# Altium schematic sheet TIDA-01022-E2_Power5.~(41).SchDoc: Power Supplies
size 431 x 279 mm; Date: Not shown in title block; ApprovedBy: Not shown in title block; CheckedBy: Not shown in title block; Author: Not shown in title block; CompanyName: Not shown in title block; DrawnBy: Avinash N; Engineer: Not shown in title block; Organization: Not shown in title block; Address1: Not shown in title block; Address2: Not shown in title block; Address3: Not shown in title block; Address4: Not shown in title block; DocumentNumber: 1; Revision: Use project parameter SCH_Rev; SheetNumber: 25; SheetTotal: 26; PageSetup: Record=PageOptions¦CenterHorizontal=True¦CenterVertical=True¦PrintScale=1.00¦XCorrection=1.00¦YCorrection=1.00¦PrintKind=0¦BorderSize=5000000¦LeftOffset=0¦BottomOffset=0¦Orientation=2¦PaperLength=1000¦PaperWidth=1000¦Scale=100¦PaperSource=15¦PrintQuality=600¦MediaType=1¦DitherType=10¦PaperKind=Letter¦PrintScaleMode=1
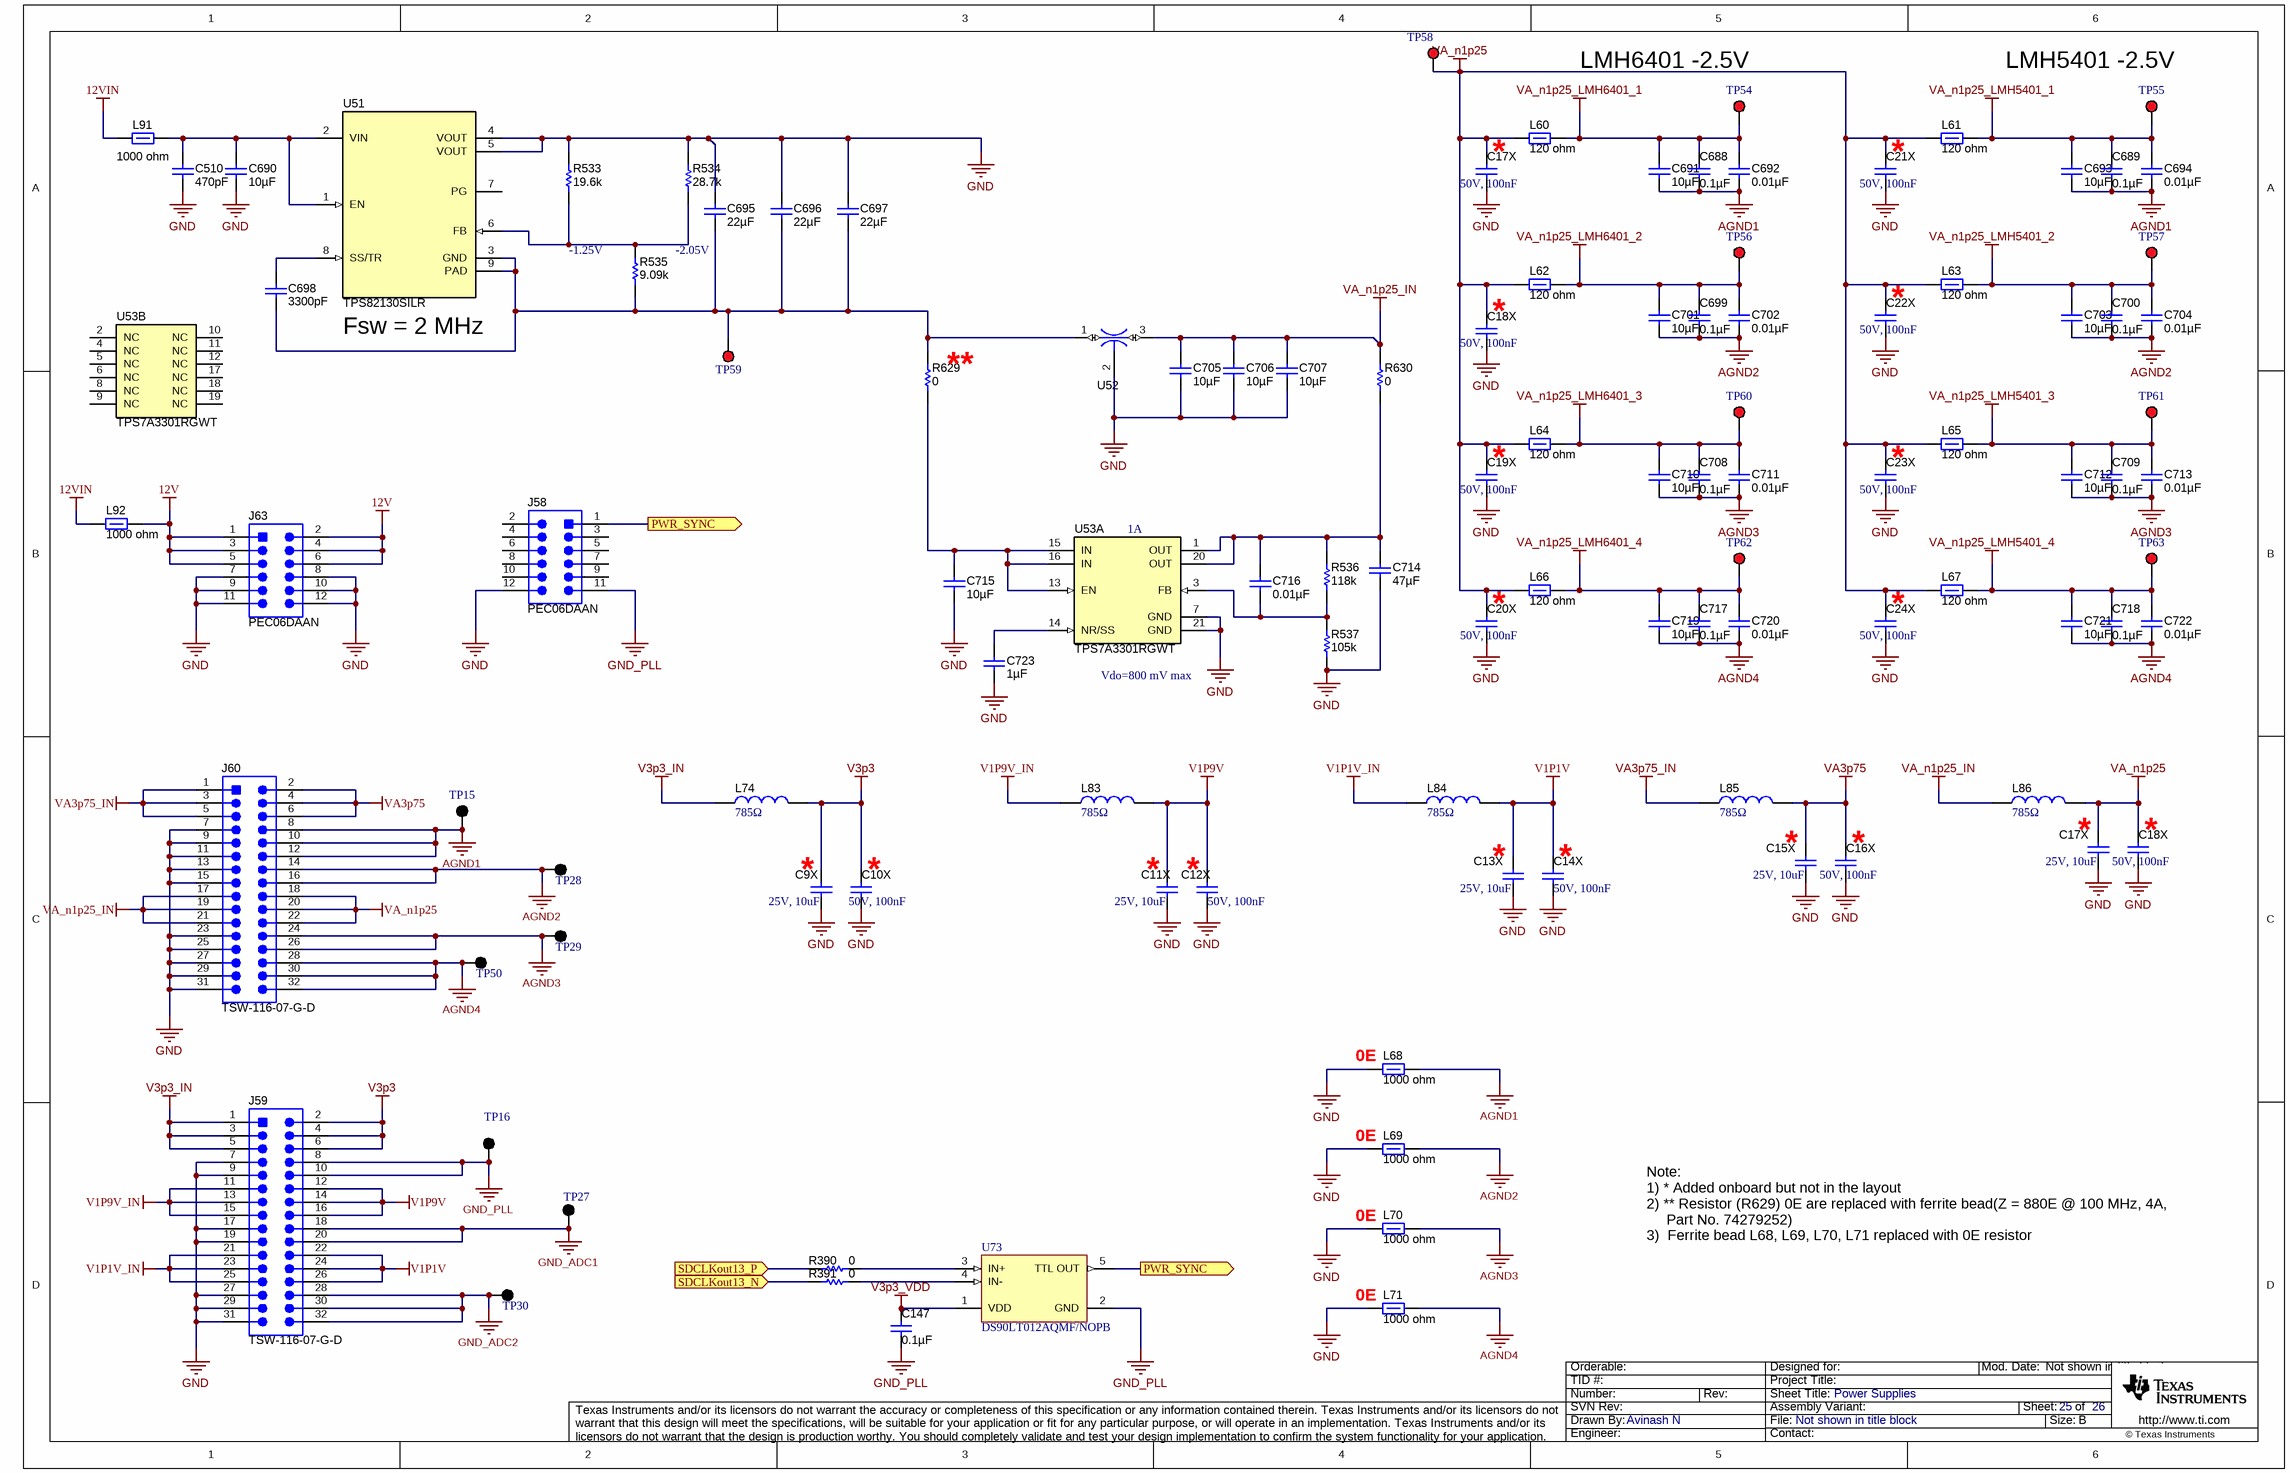
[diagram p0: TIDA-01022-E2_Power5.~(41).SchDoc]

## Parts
(Parts that share a designator on the sheet are numbered #1, #2 ... from top to bottom, then left to right.)
C9X  25V, 10uF  [1206_3.2x1.6x1.6mm]
C10X  50V, 100nF  [0603_1.6x0.8x0.8mm_Reflow Soldering]
C11X  25V, 10uF  [1206_3.2x1.6x1.6mm]
C12X  50V, 100nF  [0603_1.6x0.8x0.8mm_Reflow Soldering]
C13X  25V, 10uF  [1206_3.2x1.6x1.6mm]
C14X  50V, 100nF  [0603_1.6x0.8x0.8mm_Reflow Soldering]
C15X  25V, 10uF  [1206_3.2x1.6x1.6mm]
C16X  50V, 100nF  [0603_1.6x0.8x0.8mm_Reflow Soldering]
C17X#1  50V, 100nF  [0603_1.6x0.8x0.8mm_Reflow Soldering]
C17X#2  25V, 10uF  [1206_3.2x1.6x1.6mm]
C18X#1  50V, 100nF  [0603_1.6x0.8x0.8mm_Reflow Soldering]
C18X#2  50V, 100nF  [0603_1.6x0.8x0.8mm_Reflow Soldering]
C19X  50V, 100nF  [0603_1.6x0.8x0.8mm_Reflow Soldering]
C20X  50V, 100nF  [0603_1.6x0.8x0.8mm_Reflow Soldering]
C21X  50V, 100nF  [0603_1.6x0.8x0.8mm_Reflow Soldering]
C22X  50V, 100nF  [0603_1.6x0.8x0.8mm_Reflow Soldering]
C23X  50V, 100nF  [0603_1.6x0.8x0.8mm_Reflow Soldering]
C24X  50V, 100nF  [0603_1.6x0.8x0.8mm_Reflow Soldering]
C147  ValueDisplayed: 0.1µF  [0603]  (hidden comment: CGA3E2X7R1H104K080AA)
C510  ValueDisplayed: 470pF  [0402]  (hidden comment: GRM1555C1H471JA01D)
C688  ValueDisplayed: 0.1µF  [0603]  (hidden comment: CGA3E2X7R1H104K080AA)
C689  ValueDisplayed: 0.1µF  [0603]  (hidden comment: CGA3E2X7R1H104K080AA)
C690  ValueDisplayed: 10µF  [1206_190]  (hidden comment: C3216X7R1E106M160AE)
C691  ValueDisplayed: 10µF  [1206_190]  (hidden comment: C3216X7R1E106M160AE)
C692  ValueDisplayed: 0.01µF  [0603]  (hidden comment: GCM188R71H103KA37D)
C693  ValueDisplayed: 10µF  [1206_190]  (hidden comment: C3216X7R1E106M160AE)
C694  ValueDisplayed: 0.01µF  [0603]  (hidden comment: GCM188R71H103KA37D)
C695  ValueDisplayed: 22µF  [0805_HV]  (hidden comment: JMK212BJ226MG-T)
C696  ValueDisplayed: 22µF  [0805_HV]  (hidden comment: JMK212BJ226MG-T)
C697  ValueDisplayed: 22µF  [0805_HV]  (hidden comment: JMK212BJ226MG-T)
C698  ValueDisplayed: 3300pF  [0603]  (hidden comment: GRM1885C1H332JA01D)
C699  ValueDisplayed: 0.1µF  [0603]  (hidden comment: CGA3E2X7R1H104K080AA)
C700  ValueDisplayed: 0.1µF  [0603]  (hidden comment: CGA3E2X7R1H104K080AA)
C701  ValueDisplayed: 10µF  [1206_190]  (hidden comment: C3216X7R1E106M160AE)
C702  ValueDisplayed: 0.01µF  [0603]  (hidden comment: GCM188R71H103KA37D)
C703  ValueDisplayed: 10µF  [1206_190]  (hidden comment: C3216X7R1E106M160AE)
C704  ValueDisplayed: 0.01µF  [0603]  (hidden comment: GCM188R71H103KA37D)
C705  ValueDisplayed: 10µF  [1206_190]  (hidden comment: C3216X7R1E106M160AE)
C706  ValueDisplayed: 10µF  [1206_190]  (hidden comment: C3216X7R1E106M160AE)
C707  ValueDisplayed: 10µF  [1206_190]  (hidden comment: C3216X7R1E106M160AE)
C708  ValueDisplayed: 0.1µF  [0603]  (hidden comment: CGA3E2X7R1H104K080AA)
C709  ValueDisplayed: 0.1µF  [0603]  (hidden comment: CGA3E2X7R1H104K080AA)
C710  ValueDisplayed: 10µF  [1206_190]  (hidden comment: C3216X7R1E106M160AE)
C711  ValueDisplayed: 0.01µF  [0603]  (hidden comment: GCM188R71H103KA37D)
C712  ValueDisplayed: 10µF  [1206_190]  (hidden comment: C3216X7R1E106M160AE)
C713  ValueDisplayed: 0.01µF  [0603]  (hidden comment: GCM188R71H103KA37D)
C714  ValueDisplayed: 47µF  [0805_HV]  (hidden comment: GRM219R60G476ME44D)
C715  ValueDisplayed: 10µF  [1206_190]  (hidden comment: C3216X7R1E106M160AE)
C716  ValueDisplayed: 0.01µF  [0603]  (hidden comment: GRM188R71H103KA01D)
C717  ValueDisplayed: 0.1µF  [0603]  (hidden comment: CGA3E2X7R1H104K080AA)
C718  ValueDisplayed: 0.1µF  [0603]  (hidden comment: CGA3E2X7R1H104K080AA)
C719  ValueDisplayed: 10µF  [1206_190]  (hidden comment: C3216X7R1E106M160AE)
C720  ValueDisplayed: 0.01µF  [0603]  (hidden comment: GCM188R71H103KA37D)
C721  ValueDisplayed: 10µF  [1206_190]  (hidden comment: C3216X7R1E106M160AE)
C722  ValueDisplayed: 0.01µF  [0603]  (hidden comment: GCM188R71H103KA37D)
C723  ValueDisplayed: 1µF  [0805_HV]  (hidden comment: 08053D105KAT2A)
J58  PEC06DAAN  [CONN_PEC06DAAN]
J59  TSW-116-07-G-D  [TSW-116-07-G-D]
J60  TSW-116-07-G-D  [TSW-116-07-G-D]
J63  PEC06DAAN  [CONN_PEC06DAAN]
L60  ValueDisplayed: 120 ohm  [0603]  (hidden comment: BLM18SG121TN1D)
L61  ValueDisplayed: 120 ohm  [0603]  (hidden comment: BLM18SG121TN1D)
L62  ValueDisplayed: 120 ohm  [0603]  (hidden comment: BLM18SG121TN1D)
L63  ValueDisplayed: 120 ohm  [0603]  (hidden comment: BLM18SG121TN1D)
L64  ValueDisplayed: 120 ohm  [0603]  (hidden comment: BLM18SG121TN1D)
L65  ValueDisplayed: 120 ohm  [0603]  (hidden comment: BLM18SG121TN1D)
L66  ValueDisplayed: 120 ohm  [0603]  (hidden comment: BLM18SG121TN1D)
L67  ValueDisplayed: 120 ohm  [0603]  (hidden comment: BLM18SG121TN1D)
L68  ValueDisplayed: 1000 ohm  [1806_HighSpeed]  (hidden comment: BLM41PG102SN1L)
L69  ValueDisplayed: 1000 ohm  [1806_HighSpeed]  (hidden comment: BLM41PG102SN1L)
L70  ValueDisplayed: 1000 ohm  [1806_HighSpeed]  (hidden comment: BLM41PG102SN1L)
L71  ValueDisplayed: 1000 ohm  [1806_HighSpeed]  (hidden comment: BLM41PG102SN1L)
L74  785Ω  [WE-CBF_1812_High Current]
L83  785Ω  [WE-CBF_1812_High Current]
L84  785Ω  [WE-CBF_1812_High Current]
L85  785Ω  [WE-CBF_1812_High Current]
L86  785Ω  [WE-CBF_1812_High Current]
L91  ValueDisplayed: 1000 ohm  [1806_HighSpeed]  (hidden comment: BLM41PG102SN1L)
L92  ValueDisplayed: 1000 ohm  [1806_HighSpeed]  (hidden comment: BLM41PG102SN1L)
R390  ValueDisplayed: 0  [0402]  (hidden comment: CRCW04020000Z0ED)
R391  ValueDisplayed: 0  [0402]  (hidden comment: CRCW04020000Z0ED)
R533  ValueDisplayed: 19.6k  [0402]  (hidden comment: CRCW040219K6FKED)
R534  ValueDisplayed: 28.7k  [0402]  (hidden comment: CRCW040228K7FKED)
R535  ValueDisplayed: 9.09k  [0402]  (hidden comment: CRCW04029K09FKED)
R536  ValueDisplayed: 118k  [0402]  (hidden comment: CRCW0402118KFKED)
R537  ValueDisplayed: 105k  [0402]  (hidden comment: CRCW0402105KFKED)
R629  ValueDisplayed: 0  [1206]  (hidden comment: CRCW12060000Z0EA)
R630  ValueDisplayed: 0  [1206]  (hidden comment: CRCW12060000Z0EA)
TP15  5001  [Keystone5001]  (value not drawn)
TP16  5001  [Keystone5001]  (value not drawn)
TP27  5001  [Keystone5001]  (value not drawn)
TP28  5001  [Keystone5001]  (value not drawn)
TP29  5001  [Keystone5001]  (value not drawn)
TP30  5001  [Keystone5001]  (value not drawn)
TP50  5001  [Keystone5001]  (value not drawn)
TP54  5000  [Keystone5000]  (value not drawn)
TP55  5000  [Keystone5000]  (value not drawn)
TP56  5000  [Keystone5000]  (value not drawn)
TP57  5000  [Keystone5000]  (value not drawn)
TP58  5000  [Keystone5000]  (value not drawn)
TP59  5000  [Keystone5000]  (value not drawn)
TP60  5000  [Keystone5000]  (value not drawn)
TP61  5000  [Keystone5000]  (value not drawn)
TP62  5000  [Keystone5000]  (value not drawn)
TP63  5000  [Keystone5000]  (value not drawn)
U51  TPS82130SILR  [SIL0008D_SMD]
U52  NFM31PC276B0J3L  [Murata_NFM31P]  (value not drawn)
U53  TPS7A3301RGWT  [RGW0020A]  (parts A,B of 2)
U73  DS90LT012AQMF/NOPB  [MF05A_N]

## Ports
PWR_SYNC (out), SDCLKout13_N (in), SDCLKout13_P (in)

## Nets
12V: J63.1 J63.2 J63.3 J63.4 J63.5 J63.6 L92.1
12VIN: L91.1 L92.2
AGND1: C688.2 C689.2 C691.1 C692.2 C693.1 C694.2 J60.8 J60.10 J60.12 L68.2 TP15.1
AGND2: C699.2 C700.2 C701.1 C702.2 C703.1 C704.2 J60.14 J60.16 L69.2 TP28.1
AGND3: C708.2 C709.2 C710.1 C711.2 C712.1 C713.2 J60.24 J60.26 L70.2 TP29.1
AGND4: C717.2 C718.2 C719.1 C720.2 C721.1 C722.2 J60.28 J60.30 J60.32 L71.2 TP50.1
GND: C9X.1 C10X.1 C11X.1 C12X.1 C13X.1 C14X.1 C15X.1 C16X.1 C17X#1.1 C17X#2.1 C18X#1.1 C18X#2.1 C19X.1 C20X.1 C21X.1 C22X.1 C23X.1 C24X.1 C510.2 C690.2 C695.1 C696.1 C697.1 C705.1 C706.1 C707.1 C714.2 C715.1 C723.2 J58.12 J59.7 J59.9 J59.17 J59.19 J59.27 J59.29 J59.31 J60.7 J60.9 J60.11 J60.13 J60.15 J60.23 J60.25 J60.27 J60.29 J60.31 J63.7 J63.8 J63.9 J63.10 J63.11 J63.12 L68.1 L69.1 L70.1 L71.1 R533.2 R534.2 R537.1 U51.4(VOUT) U51.5(VOUT) U52.2 U53.7(GND) U53.21(GND)
GND_ADC1: J59.18 J59.20 TP27.1
GND_ADC2: J59.28 J59.30 J59.32 TP30.1
GND_PLL: C147.2 J58.11 J59.8 J59.10 TP16.1 U73.2(GND)
V1P1V: C13X.2 C14X.2 J59.22 J59.24 J59.26 L84.2
V1P1V_IN: J59.21 J59.23 J59.25 L84.1
V1P9V: C11X.2 C12X.2 J59.12 J59.14 J59.16 L83.2
V1P9V_IN: J59.11 J59.13 J59.15 L83.1
V3p3: C9X.2 C10X.2 J59.2 J59.4 J59.6 L74.2
V3p3_IN: J59.1 J59.3 J59.5 L74.1
V3p3_VDD: C147.1 U73.1(VDD)
VA3p75: C15X.2 C16X.2 J60.2 J60.4 J60.6 L85.2
VA3p75_IN: J60.1 J60.3 J60.5 L85.1
VA_n1p25: C17X#1.2 C17X#2.2 C18X#1.2 C18X#2.2 C19X.2 C20X.2 C21X.2 C22X.2 C23X.2 C24X.2 J60.18 J60.20 J60.22 L60.1 L61.1 L62.1 L63.1 L64.1 L65.1 L66.1 L67.1 L86.2 TP58.1
VA_n1p25_IN: C705.2 C706.2 C707.2 J60.17 J60.19 J60.21 L86.1 R630.2 U52.3
VA_n1p25_LMH5401_1: C689.1 C693.2 C694.1 L61.2 TP55.1
VA_n1p25_LMH5401_2: C700.1 C703.2 C704.1 L63.2 TP57.1
VA_n1p25_LMH5401_3: C709.1 C712.2 C713.1 L65.2 TP61.1
VA_n1p25_LMH5401_4: C718.1 C721.2 C722.1 L67.2 TP63.1
VA_n1p25_LMH6401_1: C688.1 C691.2 C692.1 L60.2 TP54.1
VA_n1p25_LMH6401_2: C699.1 C701.2 C702.1 L62.2 TP56.1
VA_n1p25_LMH6401_3: C708.1 C710.2 C711.1 L64.2 TP60.1
VA_n1p25_LMH6401_4: C717.1 C719.2 C720.1 L66.2 TP62.1
PWR_SYNC: J58.1 U73.5(TTL_OUT) ; port PWR_SYNC
SDCLKout13_N: R391.1 ; port SDCLKout13_N
SDCLKout13_P: R390.1 ; port SDCLKout13_P
NetC510_1: C510.1 C690.1 L91.2 U51.1(EN) U51.2(VIN)
NetC695_2: C695.2 C696.2 C697.2 C698.1 R535.1 R629.2 TP59.1 U51.3(GND) U51.9(PAD) U52.1
NetC698_2: C698.2 U51.8(SS/TR)
NetC714_1: C714.1 C716.1 R536.2 R630.1 U53.1(OUT) U53.20(OUT)
NetC715_2: C715.2 R629.1 U53.13(EN) U53.15(IN) U53.16(IN)
NetC716_2: C716.2 R536.1 R537.2 U53.3(FB)
NetC723_1: C723.1 U53.14(NR/SS)
NetR390_2: R390.2 U73.3(IN+)
NetR391_2: R391.2 U73.4(IN-)
NetR533_1: R533.1 R534.1 R535.2 U51.6(FB)

Not connected (* = marked no-connect by the designer): J58 2 3 4 5 6 7 8 9 10; U51 7(PG); U53 2(NC) 4(NC) 5(NC) 6(NC) 8(NC) 9(NC) 10(NC) 11(NC) 12(NC) 17(NC) 18(NC) 19(NC)

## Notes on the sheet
- (near TP54) LMH6401 -2.5V
- (near TP55) LMH5401 -2.5V
- (near C17X#1) *
- (near C21X) *
- (near R535) -1.25V
- -2.05V
- (near C22X) *
- (near U51) Fsw = 2 MHz
- (near R629) *
- (near C18X#1) *
- (near C19X) *
- (near C23X) *
- (near U53) 1A
- (near C20X) *
- (near C24X) *
- (near U53) Vdo=800 mV max
- (near C17X#2) *
- (near C18X#2) *
- (near C9X) *
- (near C10X) *
- (near C11X) *
- (near C12X) *
- (near C13X) *
- (near C14X) *
- (near C15X) *
- (near C16X) *
- (near L68) 0E
- (near L69) 0E
- (near L70) 0E
- (near L71) 0E
- Note:
  1) * Added onboard but not in the layout
  2) ** Resistor (R629) 0E are replaced with ferrite bead(Z = 880E @ 100 MHz, 4A,
  Part No. 74279252)
  3)  Ferrite bead L68, L69, L70, L71 replaced with 0E resistor

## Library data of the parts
C9X C11X C13X C15X C17X#2 = 885012208069: WCAP-CSGP Ceramic Capacitors, 1206, X7R, 25V, 10uF; Rated Voltage: 25V DC
C10X C12X C14X C16X C17X#1 C18X#1 C18X#2 C19X C20X C21X C22X C23X C24X = 885012206095: WCAP-CSGP Ceramic Capacitors, 0603, X7R, 50V, 100nF; Rated Voltage: 50V DC
C147 C688 C689 C699 C700 C708 C709 C717 C718 = CGA3E2X7R1H104K080AA: CAP, CERM, 0.1 µF, 50 V, +/- 10%, X7R, AEC-Q200 Grade 1, 0603; Manufacturer: TDK; Polarized: N; CompType: Capacitor; Value: 0.1uF; U/M: EA; Cap_F: 0.0000001; Tolerance_%: 10; ESR_ohm: 0.0296; Value1: 0.0296 ohm; VDC_V: 50; Value2: 50V; IRMS_A: 0.97199; TaMin_C: -55; TaMax_C: 125; SizeArea_mm2: 1.28; SizeAreaWB_mm2: 4.68; SizeX_mm: 1.6; SizeY_mm: 0.8; SizeZ_mm: 1; AEC Category: Q200; AEC Qualified: Y
C510 = GRM1555C1H471JA01D: CAP, CERM, 470 pF, 50 V, +/- 5%, C0G/NP0, 0402; Manufacturer: MuRata; Polarized: N; CompType: Capacitor; Value: 470pF; U/M: EA; Cap_F: 0.00000000047; Tolerance_%: 5; Value1: Unknown; VDC_V: 50; Value2: 50V; TaMin_C: -55; TaMax_C: 125; SizeArea_mm2: 0.5; SizeAreaWB_mm2: 3; SizeX_mm: 1; SizeZ_mm: 0.6; AEC Category: Q200
C690 C691 C693 C701 C703 C705-C707 C710 C712 C715 C719 C721 = C3216X7R1E106M160AE: CAP, CERM, 10 µF, 25 V, +/- 20%, X7R, 1206_190; Manufacturer: TDK; Polarized: N; CompType: Capacitor; Value: 10uF; U/M: EA; Cap_F: 0.00001; Tolerance_%: 20; Value1: Unknown; VDC_V: 25; Value2: 25V; TaMin_C: -55; TaMax_C: 125; Cap_Case: 1206; SizeArea_mm2: 5.12; SizeAreaWB_mm2: 10.92; SizeX_mm: 3.2; SizeY_mm: 1.6; SizeZ_mm: 1.9; AEC Category: Q200
C692 C694 C702 C704 C711 C713 C720 C722 = GCM188R71H103KA37D: CAP, CERM, 0.01 µF, 50 V, +/- 10%, X7R, AEC-Q200 Grade 1, 0603; Manufacturer: MuRata; Polarized: N; CompType: Capacitor; Value: 0.01uF; U/M: EA; Cap_F: 0.00000001; Tolerance_%: 10; Value1: Unknown; VDC_V: 50; Value2: 50V; TaMin_C: -55; TaMax_C: 125; SizeArea_mm2: 1.28; SizeAreaWB_mm2: 4.68; SizeX_mm: 1.6; SizeY_mm: 0.8; SizeZ_mm: 1; AEC Category: Q200; AEC Qualified: Y
C695-C697 = JMK212BJ226MG-T: CAP, CERM, 22 µF, 6.3 V, +/- 20%, X5R, 0805; Manufacturer: Taiyo Yuden; Polarized: N; CompType: Capacitor; Value: 22uF; U/M: EA; Cap_F: 0.000022; Tolerance_%: 20; Value1: Unknown; VDC_V: 6.3; Value2: 6.3V; TaMin_C: -55; TaMax_C: 85; Cap_Case: 0805; SizeArea_mm2: 2.5; SizeAreaWB_mm2: 6.75; SizeX_mm: 2; SizeY_mm: 1.25; SizeZ_mm: 1.45; AEC Category: Q200
C698 = GRM1885C1H332JA01D: CAP, CERM, 3300 pF, 50 V, +/- 5%, C0G/NP0, 0603; Manufacturer: MuRata; Polarized: N; CompType: Capacitor; Value: 3300pF; U/M: EA; Cap_F: 0.0000000033; Tolerance_%: 5; Value1: Unknown; VDC_V: 50; Value2: 50V; TaMin_C: -55; TaMax_C: 125; SizeArea_mm2: 1.28; SizeAreaWB_mm2: 4.68; SizeX_mm: 1.6; SizeY_mm: 0.8; SizeZ_mm: 1; AEC Category: Q200
C714 = GRM219R60G476ME44D: CAP, CERM, 47 µF, 4 V, +/- 20%, X5R, 0805; Manufacturer: MuRata; Polarized: N; CompType: Capacitor; Value: 47uF; U/M: EA; Cap_F: 0.000047; Tolerance_%: 20; Value1: Unknown; VDC_V: 4; Value2: 4V; TaMin_C: -55; TaMax_C: 85; Cap_Case: 0805; SizeArea_mm2: 2.5; SizeAreaWB_mm2: 6.75; SizeX_mm: 2; SizeY_mm: 1.25; SizeZ_mm: 1.45; AEC Category: Q200
C716 = GRM188R71H103KA01D: CAP, CERM, 0.01 µF, 50 V, +/- 10%, X7R, 0603; Manufacturer: MuRata; Polarized: N; CompType: Capacitor; Value: 0.01uF; U/M: EA; Cap_F: 0.00000001; Tolerance_%: 10; Value1: Unknown; VDC_V: 50; Value2: 50V; TaMin_C: -55; TaMax_C: 125; SizeArea_mm2: 1.28; SizeAreaWB_mm2: 4.68; SizeX_mm: 1.6; SizeY_mm: 0.8; SizeZ_mm: 1; AEC Category: Q200
C723 = 08053D105KAT2A: CAP, CERM, 1 µF, 25 V, +/- 10%, X5R, 0805; Manufacturer: AVX; Polarized: N; CompType: Capacitor; Value: 1uF; U/M: EA; Cap_F: 0.000001; Tolerance_%: 10; ESR_ohm: 0.012; Value1: 0.012 ohm; VDC_V: 25; Value2: 25V; TaMin_C: -55; TaMax_C: 85; Cap_Case: 0805; SizeArea_mm2: 2.5; SizeAreaWB_mm2: 6.75; SizeX_mm: 2; SizeY_mm: 1.25; SizeZ_mm: 1.45; AEC Category: Q200
J58 J63 = PEC06DAAN: Header, 100mil, 6x2, Tin, TH; Manufacturer: Sullins Connector Solutions; SymbolCreator: a0412235; Pitch_mm: 2.54; Gender: Male; Shrouded: N; Row_Count: 2; Current_A: 3; Voltage_V: 1800; Cert_UL: Y; Green_Lifecycle: Not Set; Green_REACh: Incomplete
J59 J60 = TSW-116-07-G-D: Header, 100mil, 16x2, Gold, TH; Manufacturer: Samtec; SymbolCreator: a0412235; Pitch_mm: 2.54; Gender: Male; Shrouded: N; Row_Count: 2; Current_A: 6.3; Voltage_V: 550; Cert_CSA: Y; Green_Lifecycle: Active; Green_REACh: Passed
L60-L67 = BLM18SG121TN1D: Ferrite Bead, 120 ohm @ 100 MHz, 3 A, 0603; Manufacturer: MuRata; Value: 120 ohm; Imax_A: 3; DCR_ohm: 0.025; Value1: 0.025 ohm; Value2: 3A; SizeAreaWB_mm2: 4.68; SizeArea_mm2: 1.28; SizeX_mm: 1.6; SizeY_mm: 0.8; SizeZ_mm: 1; ZTyp@100MHz_Ohm: 120
L68-L71 L91 L92 = BLM41PG102SN1L: Ferrite Bead, 1000 ohm @ 100 MHz, 1.5 A, 1806; Manufacturer: MuRata; Imax_A: 1.5; DCR_ohm: 0.09; Value1: 0.09 ohm; Value2: 1.5A; SizeAreaWB_mm2: 14.3; SizeArea_mm2: 7.2; SizeX_mm: 4.5; SizeY_mm: 1.6; SizeZ_mm: 1.85; ZTyp@100MHz_Ohm: 1000
L74 L83-L86 = WE-CBF, 742792515: WE-CBF SMD EMI Suppression Ferrite Bead, 1812, 785Ω; Type: High Current
R390 R391 = CRCW04020000Z0ED: RES, 0, 5%, 0.063 W, 0402; Manufacturer: Vishay-Dale; CompType: Resistor; Value: 0; Value_Code: 0000; Tolerance_%: 5; Power_W: 0.063; Value2: 0.063W; VDC_V: 50; TempCo: 200 ppm/C; SizeArea_mm2: 0.5; SizeX_mm: 1; SizeZ_mm: 0.6; EIA_Code: E24; U/M: EA; AEC Category: Q200
R533 = CRCW040219K6FKED: RES, 19.6 k, 1%, 0.063 W, 0402; Manufacturer: Vishay-Dale; CompType: Resistor; Value: 19.6k; Res_ohm: 19600; Value_Code: 19k6; Tolerance_%: 1; Power_W: 0.063; Value2: 0.063W; VDC_V: 50; TempCo: 100 ppm/C; SizeArea_mm2: 0.5; SizeZ_mm: 0.6; EIA_Code: E96; U/M: EA; AEC Category: Q200
R534 = CRCW040228K7FKED: RES, 28.7 k, 1%, 0.063 W, 0402; Manufacturer: Vishay-Dale; CompType: Resistor; Value: 28.7k; Res_ohm: 28700; Value_Code: 28k7; Tolerance_%: 1; Power_W: 0.063; Value2: 0.063W; VDC_V: 50; TempCo: 100 ppm/C; SizeArea_mm2: 0.5; SizeZ_mm: 0.6; EIA_Code: E96; U/M: EA; AEC Category: Q200
R535 = CRCW04029K09FKED: RES, 9.09 k, 1%, 0.063 W, 0402; Manufacturer: Vishay-Dale; CompType: Resistor; Value: 9.09k; Res_ohm: 9090; Value_Code: 9k09; Tolerance_%: 1; Power_W: 0.063; Value2: 0.063W; VDC_V: 50; TempCo: 100 ppm/C; SizeArea_mm2: 0.5; SizeZ_mm: 0.6; EIA_Code: E96; U/M: EA; AEC Category: Q200
R536 = CRCW0402118KFKED: RES, 118 k, 1%, 0.063 W, 0402; Manufacturer: Vishay-Dale; CompType: Resistor; Value: 118k; Res_ohm: 118000; Tolerance_%: 1; Power_W: 0.063; Value2: 0.063W; VDC_V: 50; TempCo: 100 ppm/C; SizeArea_mm2: 0.5; SizeZ_mm: 0.6; EIA_Code: E96; U/M: EA; AEC Category: Q200
R537 = CRCW0402105KFKED: RES, 105 k, 1%, 0.063 W, 0402; Manufacturer: Vishay-Dale; CompType: Resistor; Value: 105k; Res_ohm: 105000; Tolerance_%: 1; Power_W: 0.063; Value2: 0.063W; VDC_V: 50; TempCo: 100 ppm/C; SizeArea_mm2: 0.5; SizeZ_mm: 0.6; EIA_Code: E96; U/M: EA; AEC Category: Q200
R629 R630 = CRCW12060000Z0EA: RES, 0, 5%, 0.25 W, 1206; Manufacturer: Vishay-Dale; CompType: Resistor; Value: 0; Value_Code: 0000; Tolerance_%: 5; Power_W: 0.25; Value2: 0.25W; VDC_V: 200; TempCo: 200 ppm/C; SizeArea_mm2: 5.12; SizeX_mm: 3.2; SizeY_mm: 1.6; SizeZ_mm: 1.35; EIA_Code: E24; U/M: EA; AEC Category: Q200
TP15 TP16 TP27-TP30 TP50 = 5001: Test Point, Miniature, Black, TH; Manufacturer: Keystone; CompType: Test Point Loop; ContactFinish: Silver; Green_Lifecycle: Active; Green_REACh: Passed
TP54-TP63 = 5000: Test Point, Miniature, Red, TH; Manufacturer: Keystone; CompType: Test Point Loop; ContactFinish: Silver; Green_Lifecycle: Active; Green_REACh: Passed
U51 = TPS82130SILR: 3-A 17V Step-down Converter Module with Integrated Inductor, SIL0008D (uSIP-8); Alternate PartNumber: TPS82130SILT; Manufacturer: Texas Instruments; SymbolCreator: Altium; SizeArea_mm2: 12.25; SizeAreaWB_mm2: 20.25; SizeX_mm: 3.5; SizeZ_mm: 1.53; CompType: IC; U/M: EA
U52 = NFM31PC276B0J3L: FILTER LC HIGH FREQ 27uF 1206; Manufacturer: MuRata; SymbolCreator: Altium
U53 = TPS7A3301RGWT: Single Output High PSRR LDO, 1 A, Adjustable -1.18 to -33 V Output, -3 to -36 V Input, with Ultra-Low Noise, 20-pin VQFN (RGW), -40 to 125 degC, Green (RoHS & no Sb/Br); Manufacturer: Texas Instruments; Alternate PartNumber: Equivalent; Accuracy(%): 1.5; Iout(Max)(A): 1; Iq(Typ)(mA): 0.21; SubFamily: Single Channel LDO; Vdo(Typ)(mV): 290
U73 = DS90LT012AQMF/NOPB: Automotive LVDS Differential Line Receiver, 5-pin SOT-23, Pb-Free; Manufacturer: Texas Instruments; PackageTopMarking: N03Q*XTT; PowerWise: N; CompType: Interface IC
